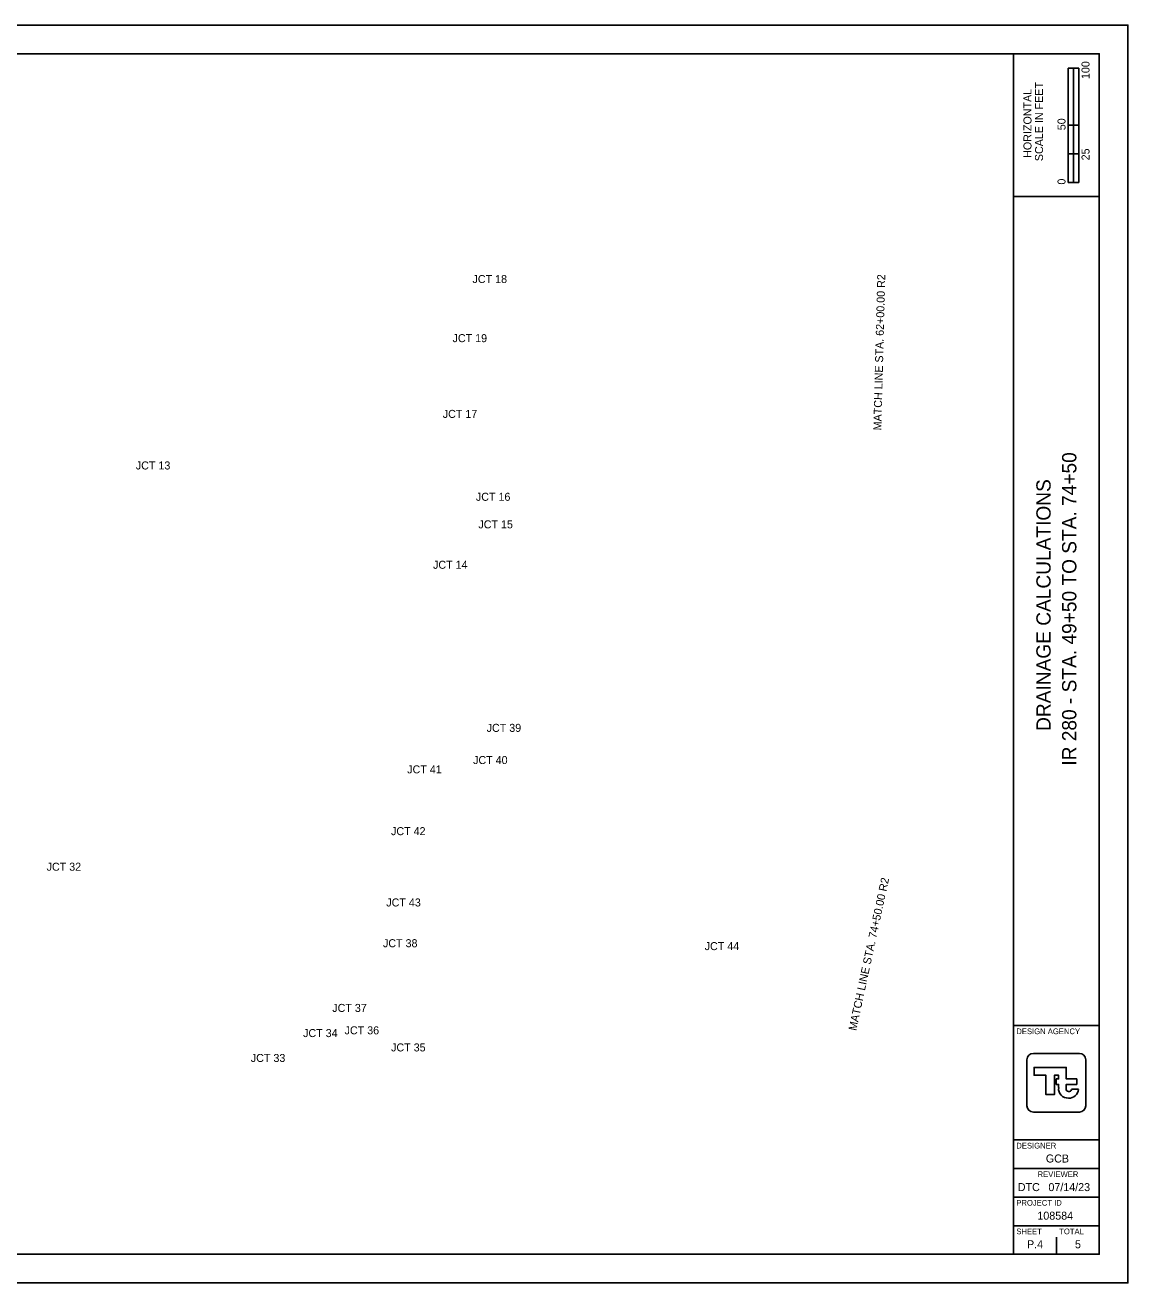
# Model space of a CAD drawing. Extents: x -3.8 to 34, y -12.8 to 22.
# Drawn here: x 14.72 to 34, y 0 to 22 of the extents above; entities that cross this region are included whole.
import ezdxf

# ---------------------------------------------------------------- set-up
doc = ezdxf.new("R2010")
doc.units = 0
for name, color, linetype in [('Default', 7, 'Continuous'), ('RS_Raster2', 7, 'Continuous'), ('SC_Scratch1', 7, 'Continuous'), ('SV_X_Shot_Marker', 7, 'Continuous')]:
    doc.layers.add(name, color=color, linetype=linetype)

msp = doc.modelspace()

# ---------------------------------------------------------------- linework, layer by layer
at = {"layer": 'RS_Raster2'}
msp.add_lwpolyline([(0, 0), (34, 0), (34, 22), (0, 22)], close=True, dxfattribs=at)
at = {"layer": 'SC_Scratch1'}
for p, q in [((32, 0.5), (32, 21.5)), ((32, 19), (33.5, 19)), ((32, 4.5), (33.5, 4.5)), ((32, 2.5), (33.5, 2.5)), ((32, 2), (33.5, 2)), ((32, 1.5), (33.5, 1.5)), ((32, 1), (33.5, 1))]:
    msp.add_line(p, q, dxfattribs=at)
msp.add_lwpolyline([(1.5, 21.5), (33.5, 21.5), (33.5, 0.5), (1.5, 0.5)], close=True, dxfattribs=at)
at = {"layer": 'SV_X_Shot_Marker'}
for p, q in [((32.957, 19.25), (32.957, 21.25)), ((33.144, 21.25), (32.957, 21.25)), ((32.957, 20.25), (32.957, 21.25)), ((32.957, 21.25), (33.05, 21.25)), ((33.05, 21.25), (33.051, 21.25)), ((33.051, 21.25), (33.051, 20.25)), ((33.144, 21.25), (33.144, 19.25)), ((33.051, 20.25), (32.957, 20.25)), ((33.143, 20.25), (33.05, 20.25)), ((33.05, 20.25), (33.05, 19.75)), ((33.143, 19.75), (33.143, 20.25)), ((33.05, 19.75), (32.957, 19.75)), ((32.957, 19.75), (32.957, 19.25)), ((33.05, 19.25), (33.05, 19.75)), ((33.05, 19.75), (33.143, 19.75)), ((33.144, 19.25), (32.957, 19.25)), ((32.957, 19.25), (33.05, 19.25)), ((32.75, 3.5), (32.75, 3.5)), ((32.791, 3.415), (32.791, 3.415)), ((33.136, 3.385), (33.015, 3.385)), ((32.375, 0.675), (32.375, 0.675)), ((32.75, 0.5), (32.75, 0.8))]:
    msp.add_line(p, q, dxfattribs=at)
for points in [[(32.348, 4.014), (33.152, 4.014)], [(32.236, 3.099), (32.236, 3.901)], [(32.922, 3.399), (32.922, 3.47), (33.107, 3.47), (33.107, 3.568), (32.922, 3.568), (32.922, 3.768), (32.361, 3.768), (32.361, 3.632), (32.566, 3.632), (32.566, 3.294), (32.715, 3.294), (32.715, 3.63), (32.79, 3.63), (32.79, 3.568), (32.748, 3.568), (32.748, 3.47), (32.79, 3.47), (32.79, 3.415), (32.791, 3.415)], [(33.264, 3.901), (33.264, 3.099)], [(33.152, 2.986), (32.348, 2.986)]]:
    msp.add_lwpolyline(points, dxfattribs=at)
for centre, radius, start, end in [((32.348, 3.901), 0.113, 90, 180), ((33.152, 3.901), 0.113, 360, 90), ((32.949, 3.392), 0.16, 171.8856, 274.8323), ((32.968, 3.392), 0.0473, 171.8856, 350.9243), ((32.976, 3.392), 0.16, 265.1677, 357.3201), ((32.348, 3.099), 0.113, 180, 270), ((33.152, 3.099), 0.113, 270, 360)]:
    msp.add_arc(centre, radius, start, end, dxfattribs=at)

# ---------------------------------------------------------------- texts
at = {"layer": 'Default'}
for s, p in [('JCT 18', (22.54, 17.489)), ('JCT 19', (22.191, 16.455)), ('JCT 17', (22.02, 15.13)), ('JCT 13', (16.652, 14.228)), ('JCT 16', (22.599, 13.68)), ('JCT 15', (22.643, 13.198)), ('JCT 14', (21.849, 12.491)), ('JCT 39', (22.787, 9.638)), ('JCT 41', (21.398, 8.912)), ('JCT 40', (22.55, 9.075)), ('JCT 42', (21.115, 7.831)), ('JCT 32', (15.092, 7.209)), ('JCT 43', (21.032, 6.584)), ('JCT 38', (20.974, 5.871)), ('JCT 44', (26.6, 5.82)), ('JCT 37', (20.087, 4.739)), ('JCT 34', (19.577, 4.299)), ('JCT 36', (20.303, 4.347)), ('JCT 35', (21.116, 4.048)), ('JCT 33', (18.663, 3.864))]:
    msp.add_text(s, height=0.14, dxfattribs=at).set_placement(p)
at = {"layer": 'SV_X_Shot_Marker'}
for s, height, rotation, p in [('100', 0.14, 90, (33.33, 21.057)), ('SCALE IN FEET', 0.14, 90, (32.517, 19.621)), ('HORIZONTAL', 0.14, 90, (32.315, 19.679)), ('50', 0.14, 90, (32.91, 20.162)), ('25', 0.14, 90, (33.33, 19.635)), ('0', 0.14, 90, (32.91, 19.211)), ('MATCH LINE STA. 62+00.00 R2', 0.14, 88.539, (29.689, 14.911)), ('IR 280 - STA. 49+50 TO STA. 74+50', 0.25, 90, (33.1, 9.047)), ('DRAINAGE CALCULATIONS', 0.25, 90, (32.65, 9.655)), ('MATCH LINE STA. 74+50.00 R2', 0.14, 77.8082, (29.25, 4.402))]:
    msp.add_text(s, height=height, rotation=rotation, dxfattribs=at).set_placement(p)
for s, height, p in [('DESIGN AGENCY', 0.1, (32.05, 4.35)), ('DESIGNER', 0.1, (32.05, 2.35)), ('GCB', 0.14, (32.566, 2.105)), ('REVIEWER', 0.1, (32.422, 1.85)), ('DTC', 0.14, (32.076, 1.605)), ('07/14/23', 0.14, (32.611, 1.605)), ('PROJECT ID', 0.1, (32.05, 1.35)), ('108584', 0.14, (32.418, 1.105)), ('SHEET', 0.1, (32.05, 0.85)), ('TOTAL', 0.1, (32.8, 0.85)), ('P.4', 0.14, (32.237, 0.605)), ('5', 0.14, (33.076, 0.605))]:
    msp.add_text(s, height=height, dxfattribs=at).set_placement(p)

doc.saveas('drawing.dxf')
